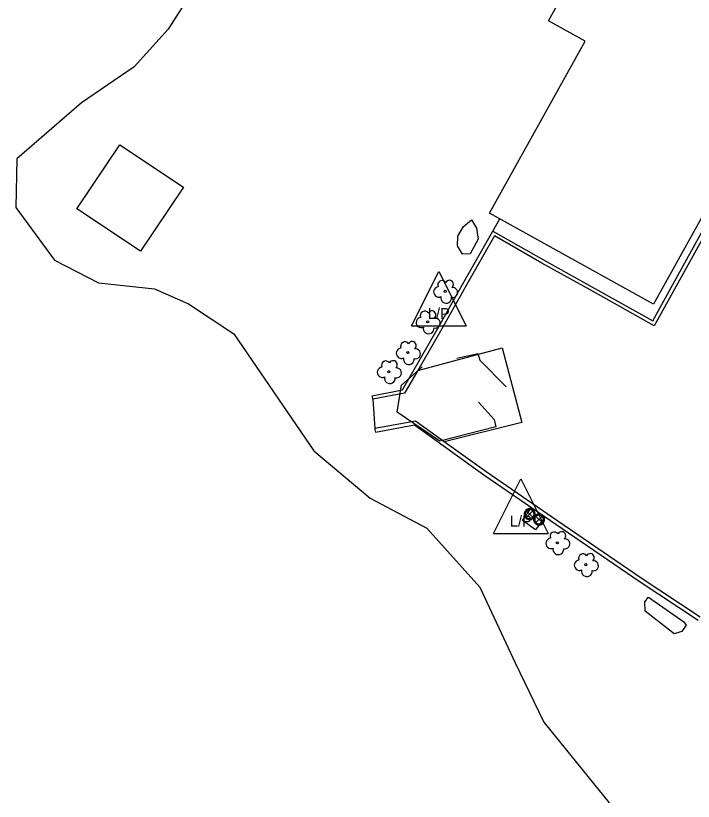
# Model space of a CAD drawing. Extents: x 2161152 to 2175754, y 602179 to 617749.
# Drawn here: x 2173530.3 to 2173654.5, y 616255.2 to 616399.3 of the extents above; entities that cross this region are included whole.
import ezdxf

# ---------------------------------------------------------------- set-up
doc = ezdxf.new("R2010")
doc.units = 0
for name, color, linetype in [('RD_EX_Bldg', 7, 'Continuous'), ('RD_EX_BldgApp_Post', 7, 'Continuous'), ('RD_EX_Conc_Curb', 7, 'Continuous'), ('RD_EX_Conc_Sidewalk', 7, 'Continuous'), ('RD_EX_Conc_Slab', 7, 'Continuous'), ('RD_EX_Fence_ChLk', 7, 'Continuous'), ('RD_EX_Fence_Gate', 7, 'Continuous'), ('RD_EX_UT', 7, 'Continuous'), ('RD_EX_VEG', 7, 'Continuous')]:
    doc.layers.add(name, color=color, linetype=linetype)

msp = doc.modelspace()

# ---------------------------------------------------------------- linework, layer by layer
at = {"layer": 'RD_EX_Bldg'}
for points in [[(2173647.25, 616346.36), (2173617.17, 616363.05), (2173634.68, 616394.61), (2173627.98, 616398.33), (2173643.55, 616426.38), (2173680.5, 616405.88), (2173666.33, 616380.34), (2173666.67, 616380.15), (2173659.83, 616367.83), (2173659.32, 616368.11), (2173647.25, 616346.36)], [(2173541.46, 616363.82), (2173549.38, 616375.56), (2173561.06, 616367.84), (2173553.14, 616356.1), (2173541.46, 616363.82)]]:
    msp.add_lwpolyline(points, dxfattribs=at)
at = {"layer": 'RD_EX_BldgApp_Post'}
for p, q in [((2173625.08, 616307.3), (2173623.95, 616308.44)), ((2173623.95, 616307.3), (2173625.08, 616308.44)), ((2173626.8, 616306.3), (2173625.67, 616307.44)), ((2173625.67, 616306.3), (2173626.8, 616307.44))]:
    msp.add_line(p, q, dxfattribs=at)
for points in [[(2173625.52, 616307.87), (2173625.51, 616308.02), (2173625.47, 616308.19), (2173625.39, 616308.35), (2173625.29, 616308.51), (2173625.15, 616308.64), (2173624.99, 616308.75), (2173624.81, 616308.83), (2173624.62, 616308.87), (2173624.43, 616308.87), (2173624.26, 616308.84), (2173624.1, 616308.78), (2173623.97, 616308.71), (2173623.84, 616308.61), (2173623.73, 616308.49), (2173623.63, 616308.34), (2173623.56, 616308.16), (2173623.52, 616307.97), (2173623.52, 616307.77), (2173623.56, 616307.58), (2173623.63, 616307.4), (2173623.73, 616307.25), (2173623.84, 616307.12), (2173623.97, 616307.03), (2173624.1, 616306.96), (2173624.26, 616306.9), (2173624.43, 616306.87), (2173624.62, 616306.87), (2173624.81, 616306.91), (2173624.99, 616306.99), (2173625.15, 616307.1), (2173625.29, 616307.23), (2173625.39, 616307.39), (2173625.47, 616307.55), (2173625.51, 616307.72), (2173625.52, 616307.87)], [(2173625.32, 616307.87), (2173625.31, 616307.99), (2173625.28, 616308.12), (2173625.22, 616308.25), (2173625.13, 616308.38), (2173625.02, 616308.49), (2173624.89, 616308.58), (2173624.75, 616308.64), (2173624.6, 616308.67), (2173624.45, 616308.67), (2173624.31, 616308.64), (2173624.19, 616308.6), (2173624.08, 616308.54), (2173623.98, 616308.47), (2173623.89, 616308.37), (2173623.81, 616308.24), (2173623.75, 616308.1), (2173623.72, 616307.95), (2173623.72, 616307.79), (2173623.75, 616307.64), (2173623.81, 616307.5), (2173623.89, 616307.37), (2173623.98, 616307.27), (2173624.08, 616307.2), (2173624.19, 616307.14), (2173624.31, 616307.09), (2173624.45, 616307.07), (2173624.6, 616307.07), (2173624.75, 616307.1), (2173624.89, 616307.16), (2173625.02, 616307.25), (2173625.13, 616307.36), (2173625.22, 616307.48), (2173625.28, 616307.62), (2173625.31, 616307.75), (2173625.32, 616307.87)], [(2173627.24, 616306.87), (2173627.22, 616307.03), (2173627.18, 616307.19), (2173627.11, 616307.35), (2173627.01, 616307.51), (2173626.87, 616307.65), (2173626.71, 616307.76), (2173626.52, 616307.83), (2173626.33, 616307.87), (2173626.15, 616307.87), (2173625.98, 616307.84), (2173625.82, 616307.79), (2173625.69, 616307.71), (2173625.56, 616307.62), (2173625.45, 616307.49), (2173625.35, 616307.34), (2173625.27, 616307.16), (2173625.24, 616306.97), (2173625.24, 616306.77), (2173625.27, 616306.58), (2173625.35, 616306.4), (2173625.45, 616306.25), (2173625.56, 616306.13), (2173625.69, 616306.03), (2173625.82, 616305.96), (2173625.98, 616305.9), (2173626.15, 616305.87), (2173626.33, 616305.87), (2173626.52, 616305.91), (2173626.71, 616305.99), (2173626.87, 616306.1), (2173627.01, 616306.23), (2173627.11, 616306.39), (2173627.18, 616306.55), (2173627.22, 616306.72), (2173627.24, 616306.87)], [(2173627.04, 616306.87), (2173627.03, 616306.99), (2173626.99, 616307.12), (2173626.94, 616307.26), (2173626.85, 616307.38), (2173626.74, 616307.49), (2173626.61, 616307.58), (2173626.47, 616307.64), (2173626.31, 616307.67), (2173626.17, 616307.67), (2173626.03, 616307.65), (2173625.91, 616307.6), (2173625.8, 616307.54), (2173625.7, 616307.47), (2173625.6, 616307.37), (2173625.52, 616307.25), (2173625.47, 616307.1), (2173625.44, 616306.95), (2173625.44, 616306.79), (2173625.47, 616306.64), (2173625.52, 616306.5), (2173625.6, 616306.38), (2173625.7, 616306.28), (2173625.8, 616306.2), (2173625.91, 616306.14), (2173626.03, 616306.1), (2173626.17, 616306.07), (2173626.31, 616306.07), (2173626.47, 616306.1), (2173626.61, 616306.16), (2173626.74, 616306.25), (2173626.85, 616306.36), (2173626.94, 616306.49), (2173626.99, 616306.62), (2173627.03, 616306.75), (2173627.04, 616306.87)]]:
    msp.add_lwpolyline(points, dxfattribs=at)
at = {"layer": 'RD_EX_Conc_Curb'}
for points in [[(2173595.64, 616329.57), (2173601.17, 616330.65), (2173607.8, 616342.15), (2173612.77, 616350.96), (2173617.79, 616359.78), (2173627.08, 616354.49), (2173636.48, 616349.24), (2173647.09, 616343.32), (2173650.77, 616349.97), (2173659.66, 616365.96)], [(2173660.24, 616365.63), (2173651.36, 616349.65), (2173647.35, 616342.41), (2173636.16, 616348.66), (2173626.76, 616353.91), (2173618.05, 616358.87), (2173613.35, 616350.64), (2173608.38, 616341.82), (2173603.98, 616334.19), (2173601.59, 616330.05), (2173595.77, 616328.92), (2173595.74, 616329.08), (2173595.64, 616329.57)], [(2173655.8, 616288.94), (2173644.97, 616296.12), (2173629.7, 616306.58), (2173616.52, 616315.62), (2173608.84, 616321.14), (2173603.58, 616324.92), (2173596.11, 616323.54)], [(2173596.11, 616323.54), (2173596.14, 616323.37), (2173596.23, 616322.88), (2173603.42, 616324.22), (2173616.14, 616315.08), (2173624.86, 616309.1), (2173627.37, 616307.37), (2173629.33, 616306.03), (2173644.6, 616295.56), (2173655.42, 616288.39)]]:
    msp.add_lwpolyline(points, dxfattribs=at)
at = {"layer": 'RD_EX_Conc_Sidewalk'}
msp.add_line((2173617.79, 616359.78), (2173619.04, 616362.01), dxfattribs=at)
at = {"layer": 'RD_EX_Conc_Slab'}
msp.add_line((2173595.77, 616328.92), (2173596.11, 616323.54), dxfattribs=at)
for points in [[(2173603.98, 616334.19), (2173619.47, 616338.35), (2173623.07, 616324.69), (2173608.84, 616321.14)], [(2173627.37, 616307.37), (2173625.6, 616305.01), (2173623.22, 616306.67), (2173624.86, 616309.1)]]:
    msp.add_lwpolyline(points, dxfattribs=at)
at = {"layer": 'RD_EX_Fence_ChLk'}
for points in [[(2173611.15, 616336.44), (2173615, 616337.34), (2173615.35, 616336.1)], [(2173618.02, 616325.21), (2173618.31, 616323.89), (2173608.04, 616321.23), (2173600.2, 616326.58), (2173601.02, 616331.52), (2173604.78, 616334.9)]]:
    msp.add_lwpolyline(points, dxfattribs=at)
at = {"layer": 'RD_EX_Fence_Gate'}
for p, q in [((2173620.23, 616331.18), (2173615.35, 616336.1)), ((2173618.02, 616325.21), (2173615.14, 616328.38))]:
    msp.add_line(p, q, dxfattribs=at)
at = {"layer": 'RD_EX_UT'}
for p, q in [((2173602.86, 616342.37), (2173607.86, 616352.37)), ((2173607.86, 616352.37), (2173612.86, 616342.37)), ((2173602.86, 616342.37), (2173612.86, 616342.37)), ((2173617.89, 616304.31), (2173622.89, 616314.31)), ((2173622.89, 616314.31), (2173627.89, 616304.31)), ((2173617.89, 616304.31), (2173627.89, 616304.31))]:
    msp.add_line(p, q, dxfattribs=at)
at = {"layer": 'RD_EX_VEG'}
for points in [[(2173567.3, 616411.07), (2173558.24, 616396.81), (2173552, 616389.86), (2173542.35, 616383.26), (2173530.49, 616373.02), (2173530.26, 616364.07), (2173537.39, 616354.41), (2173545.45, 616350.25), (2173555.7, 616349.2), (2173561.95, 616346.4), (2173570.24, 616340.92), (2173584.96, 616319.48), (2173595.27, 616310.79), (2173605.66, 616305.26), (2173615.38, 616294.48), (2173621.88, 616280.62), (2173627.12, 616269.69), (2173639.12, 616254.9)], [(2173612.22, 616355.55), (2173611.27, 616357.09), (2173611.35, 616358.83), (2173612.41, 616360.62), (2173613.83, 616361.83), (2173614.74, 616360.33), (2173615.08, 616358.28), (2173613.6, 616355.58), (2173612.22, 616355.55)], [(2173651.03, 616285.94), (2173645.7, 616290.06), (2173645.61, 616291.78), (2173646.29, 616292.62), (2173652.79, 616288.14), (2173653.24, 616287.53), (2173652.42, 616286.37), (2173651.03, 616285.94)]]:
    msp.add_lwpolyline(points, dxfattribs=at)
for centre in [(2173609.01, 616348.72), (2173605.81, 616343.11), (2173602.18, 616337.48), (2173598.7, 616333.98), (2173629.6, 616302.62), (2173634.83, 616298.6)]:
    msp.add_circle(centre, 0.188, dxfattribs=at)
for centre, radius, start, end in [((2173608.47, 616349.88), 0.813, 34.9763, 204.756), ((2173609.8, 616350), 0.746, 308.7626, 152.0467), ((2173607.84, 616348.61), 0.943, 96.4518, 294.734), ((2173610.39, 616348.51), 0.914, 256.5667, 98.1046), ((2173609.2, 616347.53), 0.988, 166.8827, 5.7589), ((2173605.27, 616344.27), 0.813, 34.9763, 204.756), ((2173606.59, 616344.39), 0.746, 308.7626, 152.0467), ((2173604.64, 616343), 0.943, 96.4518, 294.734), ((2173607.19, 616342.9), 0.914, 256.5667, 98.1046), ((2173605.99, 616341.92), 0.988, 166.8827, 5.7589), ((2173601.64, 616338.64), 0.813, 34.9763, 204.756), ((2173602.96, 616338.76), 0.746, 308.7626, 152.0467), ((2173601, 616337.36), 0.943, 96.4518, 294.734), ((2173603.56, 616337.27), 0.914, 256.5667, 98.1046), ((2173602.36, 616336.28), 0.988, 166.8827, 5.7589), ((2173597.52, 616333.87), 0.943, 96.4518, 294.734), ((2173598.16, 616335.14), 0.813, 34.9763, 204.756), ((2173599.48, 616335.26), 0.746, 308.7626, 152.0467), ((2173600.08, 616333.77), 0.914, 256.5667, 98.1046), ((2173598.88, 616332.79), 0.988, 166.8827, 5.7589), ((2173629.06, 616303.78), 0.813, 34.9763, 204.756), ((2173630.38, 616303.9), 0.746, 308.7626, 152.0467), ((2173628.42, 616302.5), 0.943, 96.4518, 294.734), ((2173630.98, 616302.41), 0.914, 256.5667, 98.1046), ((2173629.78, 616301.42), 0.988, 166.8827, 5.7589), ((2173634.29, 616299.76), 0.813, 34.9763, 204.756), ((2173635.61, 616299.88), 0.746, 308.7626, 152.0467), ((2173633.65, 616298.49), 0.943, 96.4518, 294.734), ((2173636.21, 616298.39), 0.914, 256.5667, 98.1046), ((2173635.01, 616297.41), 0.988, 166.8827, 5.7589)]:
    msp.add_arc(centre, radius, start, end, dxfattribs=at)

# ---------------------------------------------------------------- texts
at = {"layer": 'RD_EX_UT'}
for p in [(2173605.85, 616343.65), (2173620.89, 616305.59)]:
    msp.add_text('L/P', height=2, dxfattribs=at).set_placement(p)

doc.saveas('drawing.dxf')
